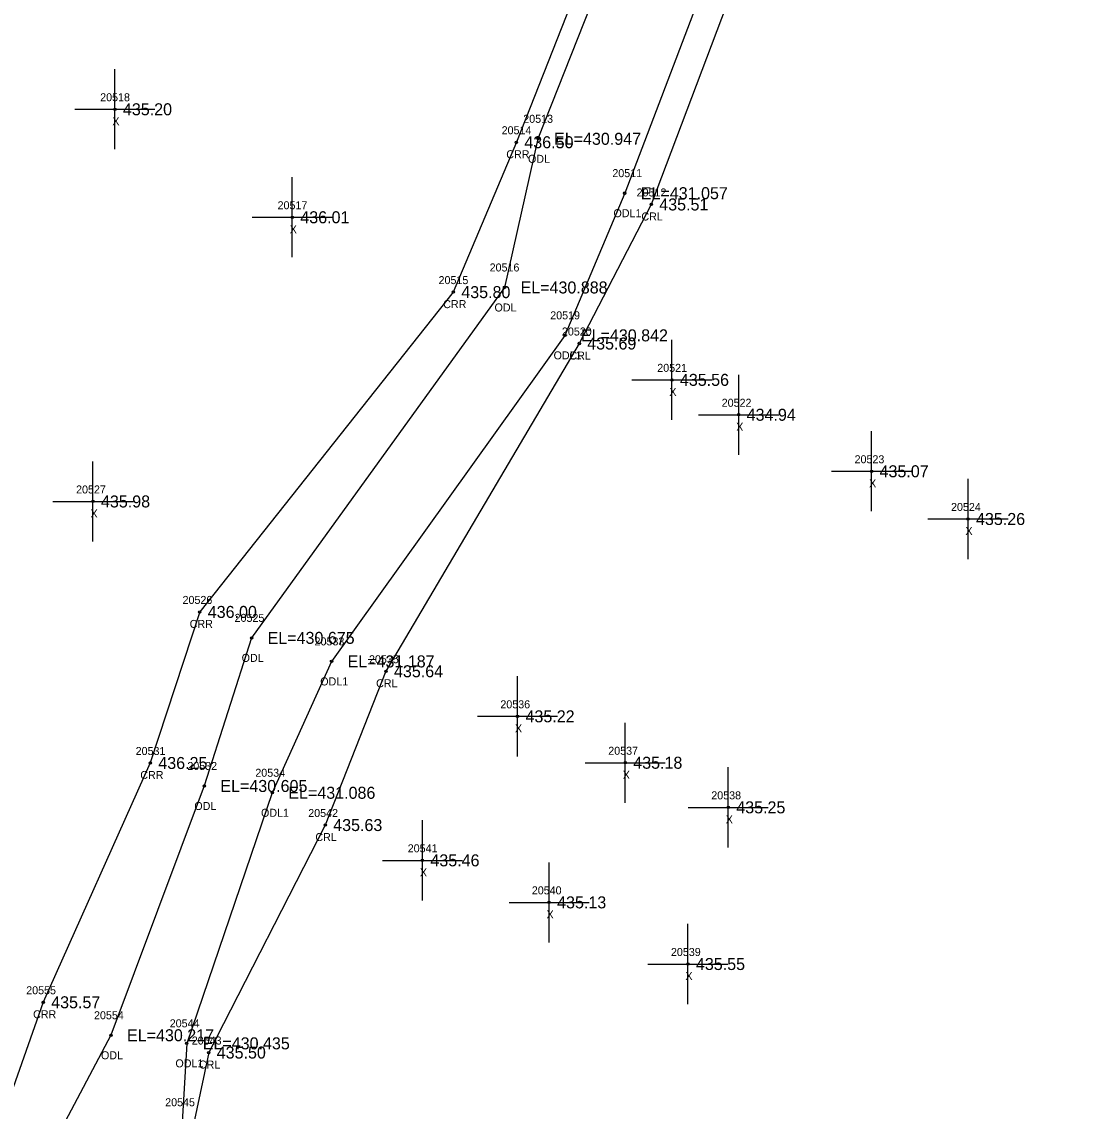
# Model space of a CAD drawing. Extents: x 1613836 to 1615109, y 777151 to 778248.
# Drawn here: x 1614505.3 to 1614639.5, y 777806.4 to 777942.5 of the extents above; entities that cross this region are included whole.
import ezdxf

# ---------------------------------------------------------------- set-up
doc = ezdxf.new("R2010")
doc.units = 0
for name, color, linetype in [('RD_EX_H2O', 7, 'Continuous'), ('RD_EX_H2O_txCode', 7, 'Continuous'), ('RD_EX_Misc', 7, 'Continuous'), ('RD_EX_Misc_txCode', 7, 'Continuous'), ('RD_EX_TX_H2O_ELEV', 7, 'Continuous'), ('RD_EX_TX_Misc_ELEV', 7, 'Continuous'), ('RD_SMD_Locator', 7, 'Continuous')]:
    doc.layers.add(name, color=color, linetype=linetype)

msp = doc.modelspace()

# ---------------------------------------------------------------- linework, layer by layer
at = {"layer": 'RD_EX_H2O'}
for points in [[(1614639.54, 778230.63), (1614634.52, 778174.88), (1614617.02, 778127.08), (1614609.96, 778108.29), (1614618.6, 778090.08), (1614618.65, 778056.48), (1614610.43, 778030), (1614589.62, 777977.97), (1614569.81, 777927.89), (1614565.63, 777909.32), (1614534.03, 777865.55), (1614528.13, 777847.05), (1614516.47, 777815.91), (1614496.55, 777778.36), (1614481.67, 777748.03), (1614471.7, 777724.98), (1614468.53, 777719.48), (1614464.55, 777708.61), (1614459.06, 777697.65), (1614451.34, 777685.51), (1614441.64, 777670.36)], [(1614634.13, 778230.42), (1614629.46, 778175.6), (1614612.2, 778126.55), (1614606.67, 778108.17), (1614610.57, 778089.24), (1614615.98, 778055.09), (1614603.68, 778033.92), (1614586.84, 777977.49), (1614567.11, 777927.46), (1614559.23, 777908.74), (1614527.56, 777868.79), (1614521.38, 777849.92), (1614508, 777820.03), (1614493.75, 777779.64), (1614479.27, 777749.87), (1614469.02, 777727.63), (1614464.37, 777721.67), (1614444.52, 777689.77), (1614435.76, 777671.49)], [(1614639.33, 778020.47), (1614638.8, 778019.37), (1614635.18, 778014.85), (1614627.32, 778013.74), (1614620.1, 778009.9), (1614613.61, 778005.82), (1614608.34, 778003.27), (1614599.89, 777971.68), (1614580.65, 777921.1), (1614573.17, 777903.34), (1614544.02, 777862.61), (1614536.62, 777846.2), (1614525.93, 777814.9), (1614525.36, 777805.04), (1614514.83, 777790.8), (1614507.45, 777775.73), (1614494.22, 777745.87), (1614477.07, 777716.66), (1614470.86, 777703.72), (1614467.03, 777692.39), (1614458.98, 777681.06), (1614454.05, 777670.72)], [(1614612.84, 778001.09), (1614602.8, 777969.59), (1614583.96, 777919.69), (1614574.96, 777902.32), (1614550.82, 777861.38), (1614543.23, 777842.17), (1614528.68, 777813.75), (1614526.1, 777801.65), (1614517.13, 777789.52), (1614510.38, 777774.58), (1614495.52, 777745.97), (1614480.57, 777714.78), (1614474.46, 777705.96), (1614477.93, 777705.13), (1614481.15, 777703.4), (1614481.27, 777700.99), (1614480.97, 777699.74), (1614478.44, 777696.16), (1614475.82, 777697.62), (1614468.32, 777689.25), (1614463.06, 777676.24), (1614459.87, 777668.19)]]:
    msp.add_lwpolyline(points, dxfattribs=at)
at = {"layer": 'RD_EX_Misc'}
for p, q in [((1614516.96, 777926.58), (1614516.96, 777936.58)), ((1614511.96, 777931.58), (1614521.96, 777931.58)), ((1614539.12, 777913.09), (1614539.12, 777923.09)), ((1614534.12, 777918.09), (1614544.12, 777918.09)), ((1614586.54, 777892.78), (1614586.54, 777902.78)), ((1614594.88, 777888.42), (1614594.88, 777898.42)), ((1614581.54, 777897.78), (1614591.54, 777897.78)), ((1614589.88, 777893.42), (1614599.88, 777893.42)), ((1614611.48, 777881.36), (1614611.48, 777891.36)), ((1614514.22, 777877.59), (1614514.22, 777887.59)), ((1614606.48, 777886.36), (1614616.48, 777886.36)), ((1614623.53, 777875.4), (1614623.53, 777885.4)), ((1614509.22, 777882.59), (1614519.22, 777882.59)), ((1614618.53, 777880.4), (1614628.53, 777880.4)), ((1614567.25, 777850.75), (1614567.25, 777860.75)), ((1614562.25, 777855.75), (1614572.25, 777855.75)), ((1614580.71, 777844.95), (1614580.71, 777854.95)), ((1614575.71, 777849.95), (1614585.71, 777849.95)), ((1614593.58, 777839.38), (1614593.58, 777849.38)), ((1614588.58, 777844.38), (1614598.58, 777844.38)), ((1614555.37, 777832.76), (1614555.37, 777842.76)), ((1614550.37, 777837.76), (1614560.37, 777837.76)), ((1614571.2, 777827.51), (1614571.2, 777837.51)), ((1614566.2, 777832.51), (1614576.2, 777832.51)), ((1614588.54, 777819.81), (1614588.54, 777829.81)), ((1614583.54, 777824.81), (1614593.54, 777824.81))]:
    msp.add_line(p, q, dxfattribs=at)
at = {"layer": 'RD_SMD_Locator'}
for centre in [(1614516.96, 777931.58), (1614567.11, 777927.46), (1614569.81, 777927.89), (1614580.65, 777921.1), (1614583.96, 777919.69), (1614539.12, 777918.09), (1614565.63, 777909.32), (1614559.23, 777908.74), (1614573.17, 777903.34), (1614574.96, 777902.32), (1614586.54, 777897.78), (1614594.88, 777893.42), (1614611.48, 777886.36), (1614514.22, 777882.59), (1614623.53, 777880.4), (1614527.56, 777868.79), (1614534.03, 777865.55), (1614544.02, 777862.61), (1614550.82, 777861.38), (1614567.25, 777855.75), (1614521.38, 777849.92), (1614580.71, 777849.95), (1614528.13, 777847.05), (1614536.62, 777846.2), (1614593.58, 777844.38), (1614543.23, 777842.17), (1614555.37, 777837.76), (1614571.2, 777832.51), (1614588.54, 777824.81), (1614508, 777820.03), (1614516.47, 777815.91), (1614525.93, 777814.9), (1614528.68, 777813.75)]:
    msp.add_circle(centre, 0.15, dxfattribs=at)

# ---------------------------------------------------------------- texts
at = {"layer": 'RD_EX_H2O_txCode'}
for s, p in [('20513', (1614567.97, 777929.89)), ('20514', (1614565.27, 777928.46)), ('CRR', (1614565.85, 777925.46)), ('ODL', (1614568.56, 777924.89)), ('20511', (1614579.1, 777923.1)), ('20512', (1614582.13, 777920.69)), ('ODL1', (1614579.24, 777918.1)), ('CRL', (1614582.73, 777917.69)), ('20516', (1614563.77, 777911.32)), ('20515', (1614557.39, 777909.74)), ('CRR', (1614557.97, 777906.74)), ('ODL', (1614564.38, 777906.32)), ('20519', (1614571.34, 777905.34)), ('20520', (1614572.8, 777903.32)), ('ODL1', (1614571.76, 777900.34)), ('CRL', (1614573.73, 777900.32)), ('20526', (1614525.41, 777869.79)), ('20525', (1614531.91, 777867.55)), ('CRR', (1614526.3, 777866.79)), ('20533', (1614541.9, 777864.61)), ('ODL', (1614532.79, 777862.55)), ('20535', (1614548.7, 777862.38)), ('ODL1', (1614542.61, 777859.61)), ('CRL', (1614549.59, 777859.38)), ('20531', (1614519.55, 777850.92)), ('20532', (1614526.01, 777849.05)), ('CRR', (1614520.13, 777847.92)), ('20534', (1614534.5, 777848.2)), ('ODL', (1614526.88, 777844.05)), ('ODL1', (1614535.21, 777843.2)), ('20542', (1614541.11, 777843.17)), ('CRL', (1614542, 777840.17)), ('20555', (1614505.88, 777821.03)), ('CRR', (1614506.74, 777818.03)), ('20554', (1614514.35, 777817.91)), ('20544', (1614523.81, 777816.9)), ('20543', (1614526.56, 777814.75)), ('ODL', (1614515.22, 777812.91)), ('ODL1', (1614524.52, 777811.9)), ('CRL', (1614527.45, 777811.75)), ('20545', (1614523.24, 777807.04))]:
    msp.add_text(s, height=1, dxfattribs=at).set_placement(p)
at = {"layer": 'RD_EX_Misc_txCode'}
for s, p in [('20518', (1614515.12, 777932.58)), ('X', (1614516.64, 777929.58)), ('20517', (1614537.28, 777919.09)), ('X', (1614538.8, 777916.09)), ('20521', (1614584.71, 777898.78)), ('X', (1614586.22, 777895.78)), ('20522', (1614592.76, 777894.42)), ('X', (1614594.57, 777891.42)), ('20523', (1614609.36, 777887.36)), ('X', (1614611.17, 777884.36)), ('20527', (1614512.11, 777883.59)), ('20524', (1614621.41, 777881.4)), ('X', (1614513.91, 777880.59)), ('X', (1614623.21, 777878.4)), ('20536', (1614565.11, 777856.75)), ('X', (1614566.94, 777853.75)), ('20537', (1614578.59, 777850.95)), ('X', (1614580.4, 777847.95)), ('20538', (1614591.46, 777845.38)), ('X', (1614593.27, 777842.38)), ('20541', (1614553.54, 777838.76)), ('X', (1614555.06, 777835.76)), ('20540', (1614569.04, 777833.51)), ('X', (1614570.88, 777830.51)), ('20539', (1614586.42, 777825.81)), ('X', (1614588.23, 777822.81))]:
    msp.add_text(s, height=1, dxfattribs=at).set_placement(p)
at = {"layer": 'RD_EX_TX_H2O_ELEV'}
for s, p in [('EL=430.947', (1614571.81, 777927.14)), ('436.50', (1614568.11, 777926.71)), ('EL=431.057', (1614582.65, 777920.35)), ('435.51', (1614584.96, 777918.94)), ('435.80', (1614560.23, 777907.99)), ('EL=430.888', (1614567.63, 777908.57)), ('EL=430.842', (1614575.17, 777902.59)), ('435.69', (1614575.96, 777901.57)), ('436.00', (1614528.56, 777868.04)), ('EL=430.675', (1614536.03, 777864.8)), ('EL=431.187', (1614546.02, 777861.86)), ('435.64', (1614551.82, 777860.63)), ('436.25', (1614522.38, 777849.17)), ('EL=430.605', (1614530.13, 777846.3)), ('EL=431.086', (1614538.62, 777845.45)), ('435.63', (1614544.23, 777841.42)), ('435.57', (1614509, 777819.28)), ('EL=430.217', (1614518.47, 777815.16)), ('EL=430.435', (1614527.93, 777814.15)), ('435.50', (1614529.68, 777813))]:
    msp.add_text(s, height=1.5, dxfattribs=at).set_placement(p)
at = {"layer": 'RD_EX_TX_Misc_ELEV'}
for s, p in [('435.20', (1614517.96, 777930.83)), ('436.01', (1614540.12, 777917.34)), ('435.56', (1614587.54, 777897.03)), ('434.94', (1614595.88, 777892.67)), ('435.07', (1614612.48, 777885.61)), ('435.98', (1614515.22, 777881.84)), ('435.26', (1614624.53, 777879.65)), ('435.22', (1614568.25, 777855)), ('435.18', (1614581.71, 777849.2)), ('435.25', (1614594.58, 777843.63)), ('435.46', (1614556.37, 777837.01)), ('435.13', (1614572.2, 777831.76)), ('435.55', (1614589.54, 777824.06))]:
    msp.add_text(s, height=1.5, dxfattribs=at).set_placement(p)

doc.saveas('drawing.dxf')
